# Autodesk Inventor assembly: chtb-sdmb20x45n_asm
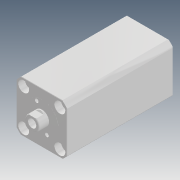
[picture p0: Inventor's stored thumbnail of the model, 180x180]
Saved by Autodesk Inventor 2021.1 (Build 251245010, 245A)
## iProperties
Company: Microsoft
Created: 2018-05
Part Number: chtb-sdmb20x45n_asm
Description: STEP AP214
Document SubType Name: Assembly
Designer: user
Title: chtb-sdmb20x45n_asm.STEP
Author: Windows
Revision Number: ÈÎºÎ
Sending System: SolidWorks 2015
Preprocessor: SwSTEP 2.0
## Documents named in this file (4)
- D:\Vault_2016\Projekty\Clamptek\Hydraulic\CHTB\CHTB-20\Inventor\CHTB-SDMB20x45N\chtb-sdmb20x45n_asm.iam
- D:\Vault_2016\Projekty\Clamptek\Hydraulic\CHTB\CHTB-20\Inventor\CHTB-SDMB20x45N\CHTB-SDMB20X45NBT.ipt
- D:\Vault_2016\Projekty\Clamptek\Hydraulic\CHTB\CHTB-20\Inventor\CHTB-SDMB20x45N\CHTB-SDMB20X45NHSG.ipt
- D:\Vault_2016\Projekty\Clamptek\Hydraulic\CHTB\CHTB-20\Inventor\CHTB-SDMB20x45N\QG_3.ipt
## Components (3 placed, 3 different names)
1. CHTB-SDMB20X45NBT_1
2. CHTB-SDMB20X45NHSG_2
3. QG_3_3
